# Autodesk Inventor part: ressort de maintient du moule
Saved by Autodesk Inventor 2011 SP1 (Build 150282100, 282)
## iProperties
Created: 2010-12
Part Number: ressort de maintient du moule
Document SubType Name: Modeling
Designer: eric
Density: 1 g/cm^3
Author: eric
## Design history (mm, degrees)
feature "Base1"
node "Solide1"
node "Corps solides"
node "Corps surfaciques"
